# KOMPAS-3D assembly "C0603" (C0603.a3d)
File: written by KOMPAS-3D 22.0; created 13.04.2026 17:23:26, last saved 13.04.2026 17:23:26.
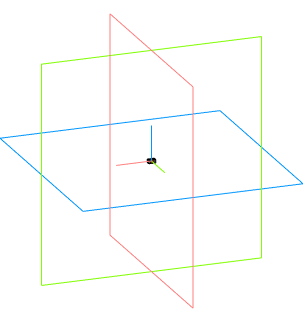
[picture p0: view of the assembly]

Document properties: Автор: Andrey; Полное имя файла: C:\Users\User1\Documents\C0603.a3d

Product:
- Component [detail]: 06035A910JAT2A  | qty 1  | source file: 06035A910JAT2A.m3d
- Part/product: C0603
    Комментарий: C0603

Referenced files in C:\Users\User1\Documents\: 06035A910JAT2A.m3d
